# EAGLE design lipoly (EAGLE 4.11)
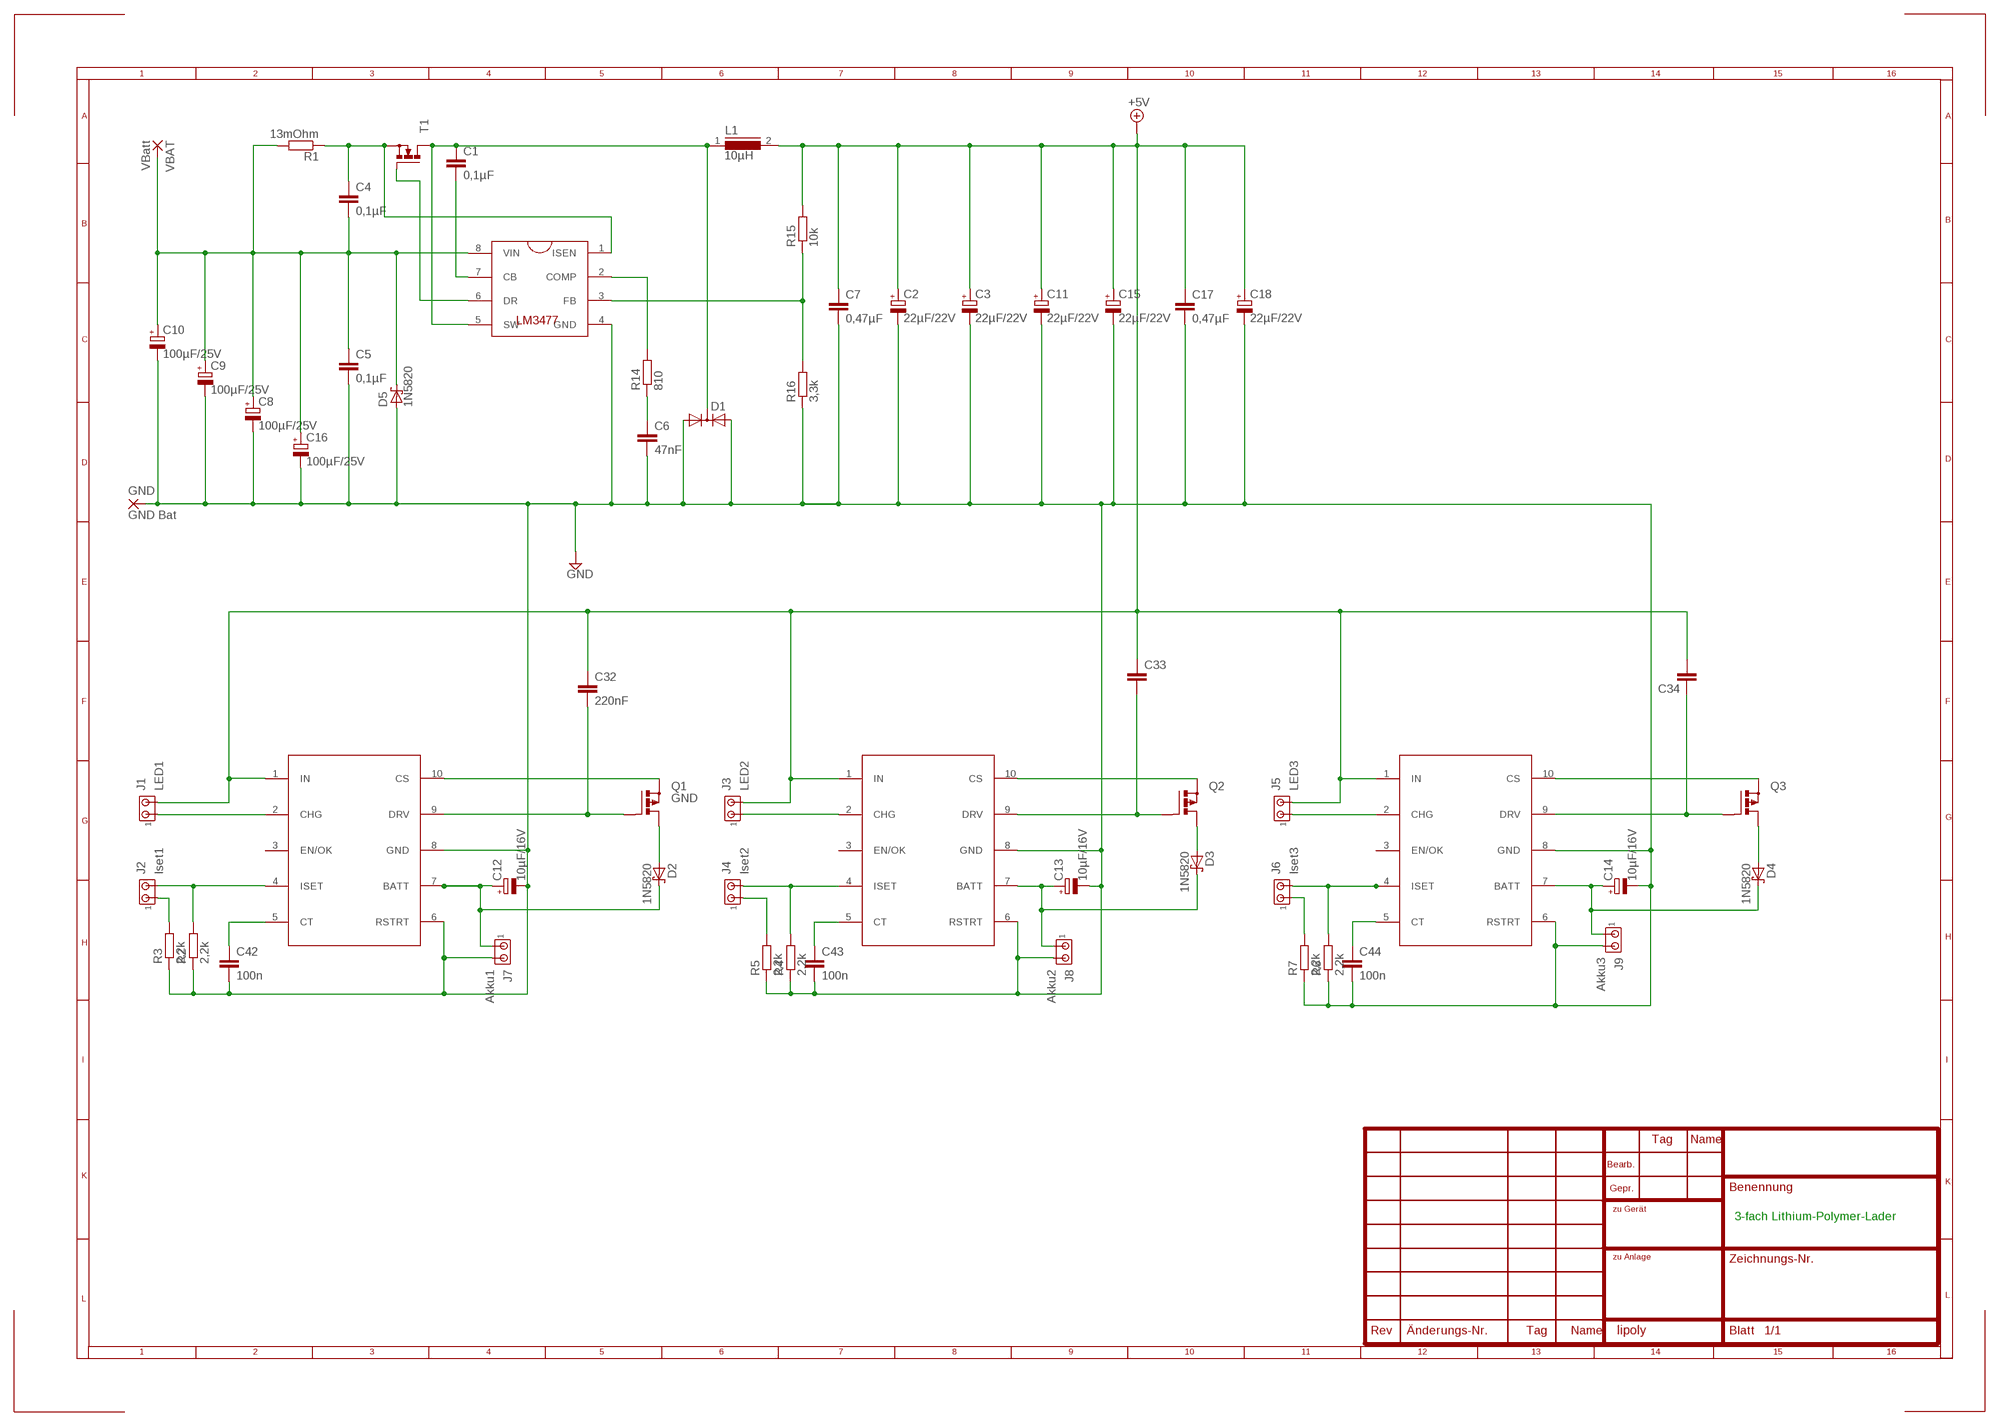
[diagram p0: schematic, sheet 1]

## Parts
C1  0,1µF  C-EU050-025X075  [C050-025X075]
C2  22µF/22V  CPOL-EUE5-6  [E5-6]
C3  22µF/22V  CPOL-EUE5-6  [E5-6]
C4  0,1µF  C-EU050-025X075  [C050-025X075]
C5  0,1µF  C-EU050-025X075  [C050-025X075]
C6  47nF  C-EU050-025X075  [C050-025X075]
C7  0,47µF  C-EU050-025X075  [C050-025X075]
C8  100µF/25V  CPOL-EUTT5D10  [TT5D10]
C9  100µF/25V  CPOL-EUTT5D10  [TT5D10]
C10  100µF/25V  CPOL-EUTT5D10  [TT5D10]
C11  22µF/22V  CPOL-EUE5-6  [E5-6]
C12  10µF/16V  CPOL-EUTAP5-60  [TAP5-60]
C13  10µF/16V  CPOL-EUTAP5-60  [TAP5-60]
C14  10µF/16V  CPOL-EUTAP5-60  [TAP5-60]
C15  22µF/22V  CPOL-EUE5-6  [E5-6]
C16  100µF/25V  CPOL-EUTT5D10  [TT5D10]
C17  0,47µF  C-EU050-025X075  [C050-025X075]
C18  22µF/22V  CPOL-EUE5-6  [E5-6]
C32  220nF  C-EU050-050X075  [C050-050X075]
C33  C-EU050-050X075  [C050-050X075]
C34  C-EU050-050X075  [C050-050X075]
C42  100n  C-EU050-025X075  [C050-025X075]
C43  100n  C-EU050-025X075  [C050-025X075]
C44  100n  C-EU050-025X075  [C050-025X075]
D1  DIODE-2AC|CATO220V  [TO220ABS]
D2  1N5820  SCHOTTKY-DIODEC4111-15  [C4111-15]
D3  1N5820  SCHOTTKY-DIODEC4111-15  [C4111-15]
D4  1N5820  SCHOTTKY-DIODEC4111-15  [C4111-15]
D5  1N5820  SCHOTTKY-DIODEC4111-15  [C4111-15]
GND  GND Bat  2,54/1,1  [2,54/1,1]
IC2  MAX1898  [UMAX10@1]
IC3  MAX1898  [UMAX10@1]
IC4  MAX1898  [UMAX10@1]
J1  LED1  MTA02-100  [10X02MTA]
J2  Iset1  MTA02-100  [10X02MTA]
J3  LED2  MTA02-100  [10X02MTA]
J4  Iset2  MTA02-100  [10X02MTA]
J5  LED3  MTA02-100  [10X02MTA]
J6  Iset3  MTA02-100  [10X02MTA]
J7  Akku1  MTA02-100  [10X02MTA]
J8  Akku2  MTA02-100  [10X02MTA]
J9  Akku3  MTA02-100  [10X02MTA]
L1  10µH  SFT830D  [SFT830D]
Q1  GND  PMOSFET_PTO220BV  [TO220BV]
Q2  PMOSFET_PTO220BV  [TO220BV]
Q3  PMOSFET_PTO220BV  [TO220BV]
R1  13mOhm  R-EU_0309/12  [0309/12]
R2  2,2k  R-EU_0207/10  [0207/10]
R3  2,2k  R-EU_0207/10  [0207/10]
R4  2,2k  R-EU_0207/10  [0207/10]
R5  2,2k  R-EU_0207/10  [0207/10]
R6  2,2k  R-EU_0207/10  [0207/10]
R7  2,2k  R-EU_0207/10  [0207/10]
R14  810  R-EU_0207/10  [0207/10]
R15  10k  R-EU_0207/10  [0207/10]
R16  3,3k  R-EU_0207/10  [0207/10]
T1  PMOSFET_NTO220BV  [TO220BV]
U$2  LM3477  [MINI-SO]
VBAT  VBatt  2,54/1,1  [2,54/1,1]

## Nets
+5V: C2.+ C3.+ C7.1 C11.+ C15.+ C17.1 C18.+ C32.1 C33.1 C34.2 IC2.1(IN) IC3.1(IN) IC4.1(IN) J1.2 J3.2 J5.2 L1.2 R15.2
+12V: C4.2 C5.1 C8.+ C9.+ C10.+ C16.+ D5.C R1.2 U$2.8(VIN) VBAT.1(P)
C42: C42.1 IC2.5(CT)
GND: C2.- C3.- C5.2 C6.2 C7.2 C8.- C9.- C10.- C11.- C12.- C13.- C14.- C15.- C16.- C17.2 C18.- C42.2 C43.2 C44.2 D1.A1 D1.A2 D5.A GND.1(P) IC2.6(RSTRT) IC2.8(GND) IC3.6(RSTRT) IC3.8(GND) IC4.6(RSTRT) IC4.8(GND) J7.2 J8.2 J9.2 R2.1 R3.1 R4.1 R5.1 R6.1 R7.1 R16.1 U$2.4(GND)
N$2: T1.G U$2.6(DR)
N$3: C4.1 R1.1 T1.S U$2.1(ISEN)
N$4: C1.1 D1.C L1.1 T1.D U$2.5(SW)
N$5: R14.2 U$2.2(COMP)
N$6: C1.2 U$2.7(CB)
N$7: IC2.10(CS) Q1.S
N$8: C6.1 R14.1
N$9: J4.1 R5.2
N$10: J6.1 R7.2
N$11: C32.2 IC2.9(DRV) Q1.G
N$12: J2.1 R3.2
N$13: R15.1 R16.2 U$2.3(FB)
N$14: C13.+ D3.C IC3.7(BATT) J8.1
N$25: C33.2 IC3.9(DRV) Q2.G
N$26: D3.A Q2.D
N$27: C12.+ D2.C IC2.7(BATT) J7.1
N$28: IC4.10(CS) Q3.S
N$29: C34.1 IC4.9(DRV) Q3.G
N$32: C14.+ D4.C IC4.7(BATT) J9.1
N$33: IC2.2(CHG) J1.1
N$34: IC2.4(ISET) J2.2 R2.2
N$35: IC3.4(ISET) J4.2 R4.2
N$36: IC4.4(ISET) J6.2 R6.2
N$37: C43.1 IC3.5(CT)
N$38: IC3.2(CHG) J3.1
N$39: C44.1 IC4.5(CT)
N$40: IC4.2(CHG) J5.1
T2: D2.A Q1.D
T3: IC3.10(CS) Q2.S
T4: D4.A Q3.D
Unconnected: IC2.3(EN/OK) IC3.3(EN/OK) IC4.3(EN/OK)

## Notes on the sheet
- 3-fach Lithium-Polymer-Lader

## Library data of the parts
C1 C4-C7 C17 C32-C34 C42-C44 = rcl:C-EU: CAPACITOR, European symbol
C2 C3 C8-C16 C18 = rcl:CPOL-EU: POLARIZED CAPACITOR, European symbol
D1 = diode:DIODE-2AC|CA: Dual DIODE Anode-Cathode|Cathode-Anode
D2-D5 = diode:SCHOTTKY-DIODE: Schottky Diode
GND VBAT = wirepad:2,54/1,1: THROUGH-HOLE PAD
IC2-IC4 = maxim:MAX1898
J1-J9 = con-amp:MTA02-100: AMP connector
L1 = inductors:SFT830D: INDUCTOR
Q1-Q3 = transistor-power:PMOSFET_P: Power MOSFET P-Channel
R1-R7 R14-R16 = rcl:R-EU_: RESISTOR, European symbol
T1 = transistor-power:PMOSFET_N: Power MOSFET N-Channel
U$2 = national:LM3477

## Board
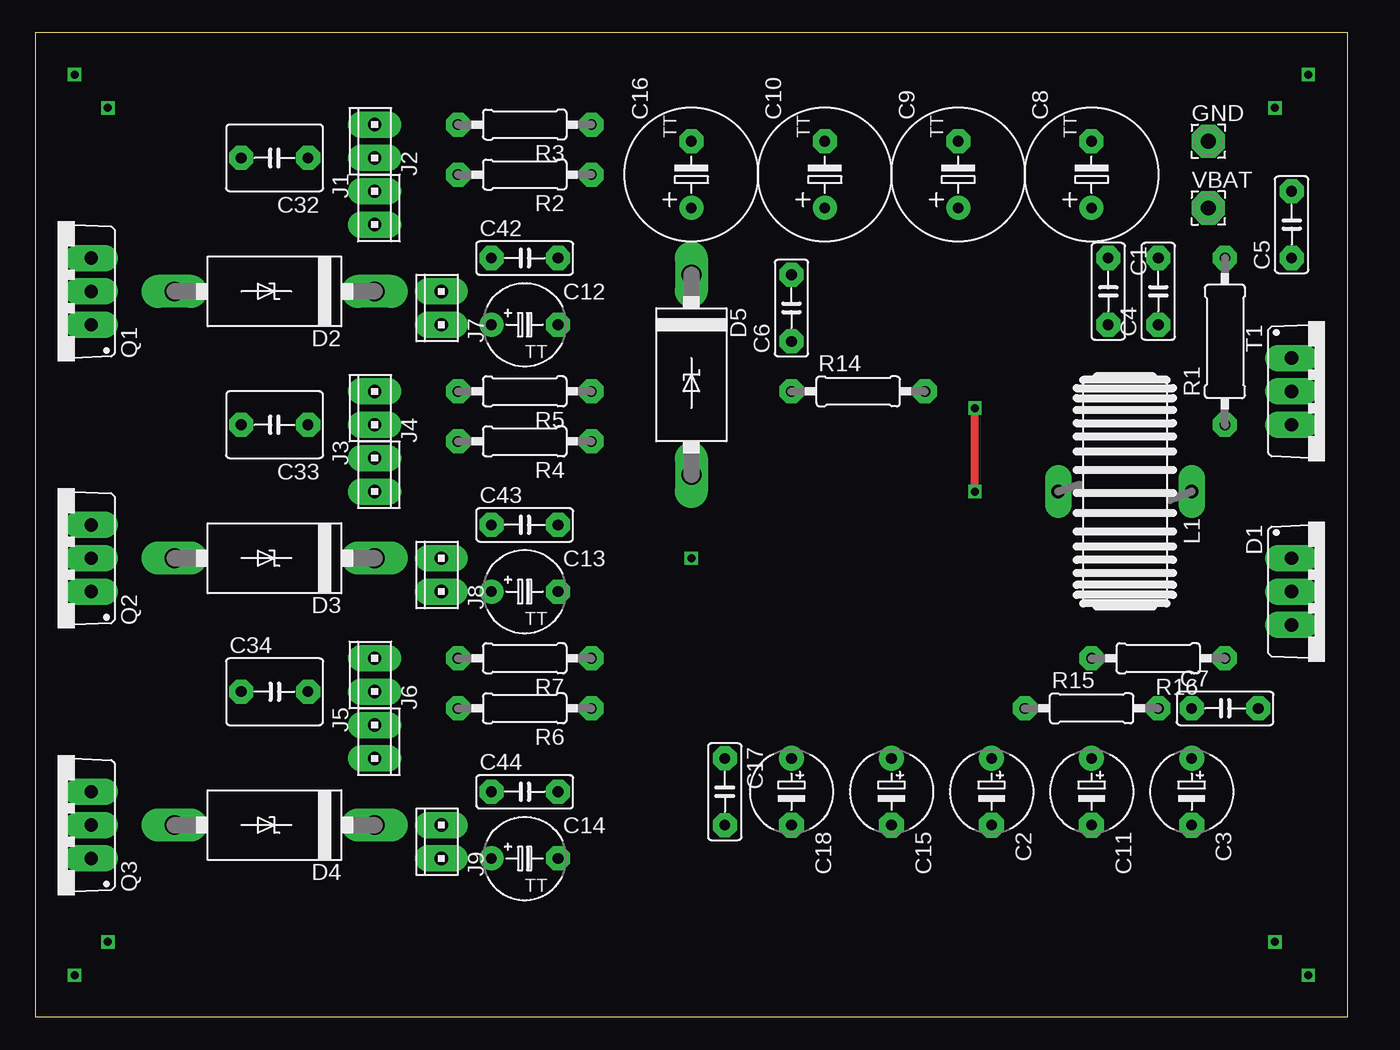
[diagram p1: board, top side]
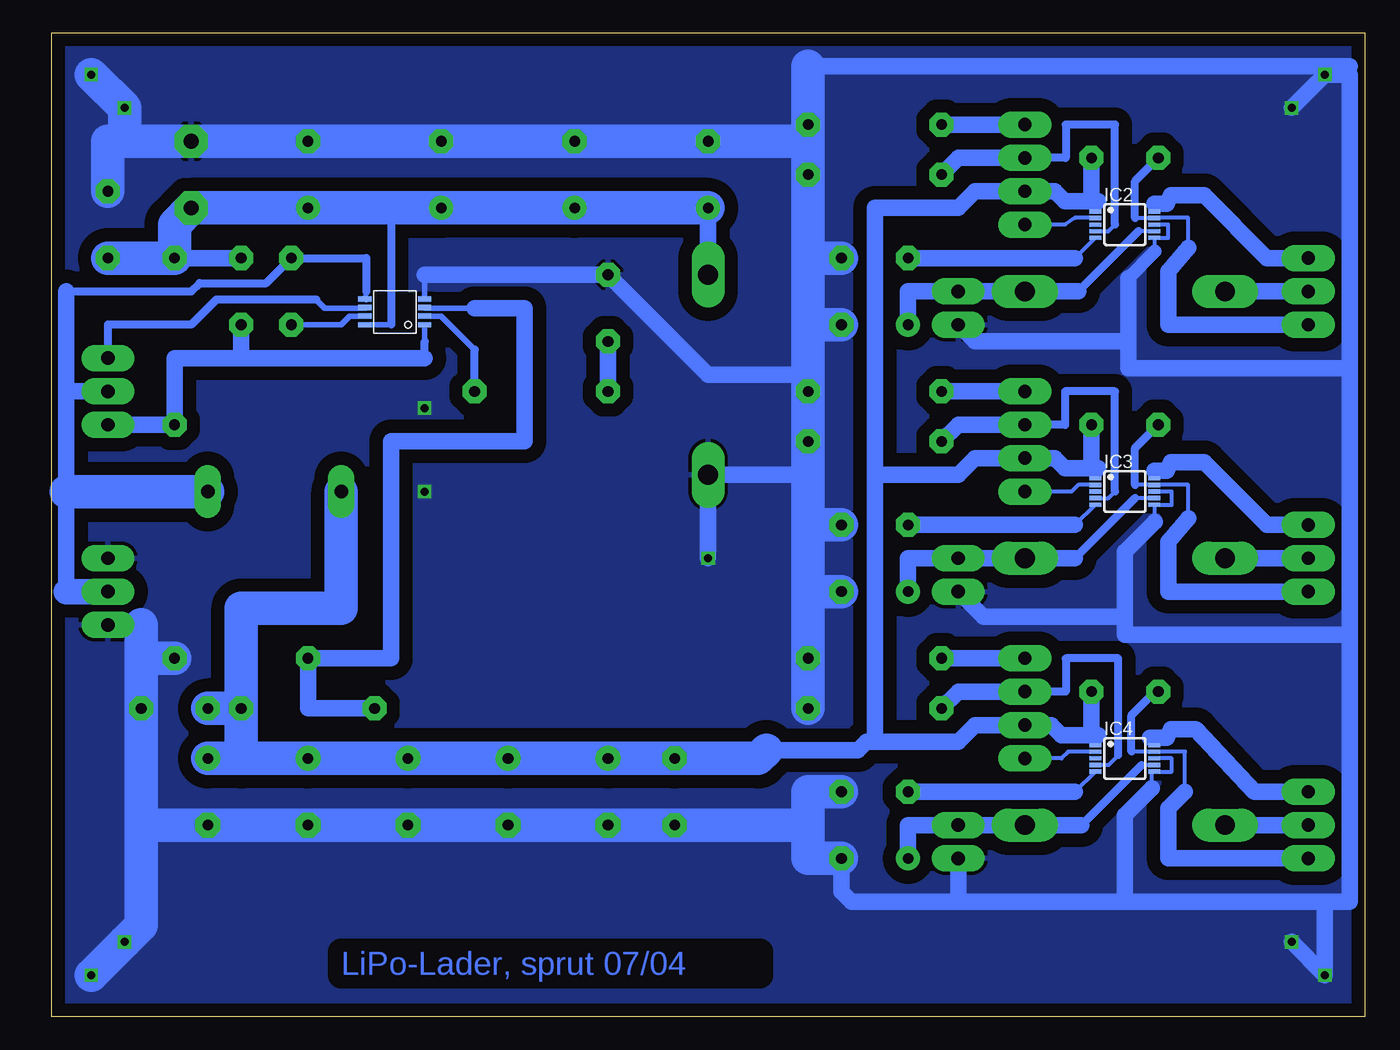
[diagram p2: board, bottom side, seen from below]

Size 100 x 74.92 mm. Coordinates in mm from the lower left corner, seen from the top.
Outline: 0,0 100,0 100,74.92 0,74.92 0,0
Copper layers (1*16): Top 0.035mm / dielectric 1.5mm / Bottom 0.035mm
Design rules "default": minimum track width 10mil, minimum drill 12mil, track to track 8mil, track to pad 8mil, pad to pad 8mil, via to via 8mil, smd to smd 8mil, copper to edge 40mil, drill to drill 8mil, minimum pad ring 20mil, minimum via ring 8mil, stop-mask expansion 4mil, vias tented up to drill 0mil, thermal gap 10mil

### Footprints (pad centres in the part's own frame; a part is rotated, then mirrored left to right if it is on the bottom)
C050-025X075 = drill 0.813 pad 1.778 octagon: 1 -2.54,0; 2 2.54,0
E5-6 = drill 0.813 pad 1.905 round: + -2.54,0 | drill 0.813 pad 1.905 octagon: - 2.54,0
TT5D10 = drill 0.813 round: + -2.54,0 | drill 0.813 octagon: - 2.54,0
TAP5-60 = drill 0.813 round: + -2.54,0 | drill 0.813 octagon: - 2.54,0
C050-050X075 = drill 0.813 octagon: 1 -2.54,0; 2 2.54,0
TO220ABS = drill 1.016 long: A1 -2.54,-2.54; A2 2.54,-2.54; C 0,-2.54
C4111-15 = drill 1.499 long: A 7.62,0; C -7.62,0
2,54/1,1 = drill 1.118 pad 2.54 octagon: 1 0,0
UMAX10@1 = smd 0.32 x 0.9: 1 -1,-2.25; 2 -0.5,-2.25; 3 0,-2.25; 4 0.5,-2.25; 5 1,-2.25; 6 1,2.25; 7 0.5,2.25; 8 0,2.25; 9 -0.5,2.25; 10 -1,2.25
10X02MTA = drill 1.016 long: 1 1.27,0; 2 -1.27,0
SFT830D = drill 1.016 long: 1 -5.08,0; 2 5.08,0
TO220BV = drill 1.016 long: D 0,-2.54; G -2.54,-2.54; S 2.54,-2.54
0309/12 = drill 0.813 octagon: 1 -6.35,0; 2 6.35,0
0207/10 = drill 0.813 pad 1.778 octagon: 1 -5.08,0; 2 5.08,0
MINI-SO = smd 1.02 x 0.41: 1 -2.54,0; 2 -2.54,-0.65; 3 -2.54,-1.3; 4 -2.54,-1.95; 5 2.01,-1.95; 6 2.01,-1.3; 7 2.01,-0.65; 8 2.01,0

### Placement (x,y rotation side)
C1  81.75,55.24 270 top
C2  72.86,17.14 270 top
C3  88.1,17.14 270 top
C4  85.56,55.24 90 top
C5  95.72,60.32 90 top
C6  57.62,53.97 90 top
C7  90.64,23.49 0 top
C8  80.48,64.13 90 top
C9  70.32,64.13 90 top
C10  60.16,64.13 90 top
C11  80.48,17.14 270 top
C12  37.3,52.7 0 top
C13  37.3,32.38 0 top
C14  37.3,12.06 0 top
C15  65.24,17.14 270 top
C16  50,64.13 90 top
C17  52.54,17.14 270 top
C18  57.62,17.14 270 top
C32  18.25,65.4 180 top
C33  18.25,45.08 180 top
C34  18.25,24.76 0 top
C42  37.3,57.78 0 top
C43  37.3,37.46 0 top
C44  37.3,17.14 0 top
D1  98.26,32.38 270 top
D2  18.25,55.24 180 top
D3  18.25,34.92 180 top
D4  18.25,14.6 180 top
D5  50,48.89 270 top
GND  89.37,66.67 0 top
IC2  18.25,60.32 270 bottom
IC3  18.25,40 270 bottom
IC4  18.25,19.68 270 bottom
J1  25.87,61.59 270 top
J2  25.87,66.67 90 top
J3  25.87,41.27 270 top
J4  25.87,46.35 90 top
J5  25.87,20.95 270 top
J6  25.87,26.03 90 top
J7  30.95,53.97 90 top
J8  30.95,33.65 90 top
J9  30.95,13.33 90 top
L1  83.02,40 180 top
Q1  1.74,55.24 90 top
Q2  1.74,34.92 90 top
Q3  1.74,14.6 90 top
R1  90.64,51.43 90 top
R2  37.3,64.13 180 top
R3  37.3,67.94 180 top
R4  37.3,43.81 180 top
R5  37.3,47.62 180 top
R6  37.3,23.49 180 top
R7  37.3,27.3 180 top
R14  62.7,47.62 0 top
R15  80.48,23.49 0 top
R16  85.56,27.3 180 top
T1  98.26,47.62 270 top
U$2  74.13,52.7 180 bottom
VBAT  89.37,61.59 0 top

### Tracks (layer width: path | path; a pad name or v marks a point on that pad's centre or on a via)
+5V
  Bottom 0.254: J3.2 25.62,42.54 | 20.52,41 20.54,41.02 | 20.52,41 IC3.1 | 20.52,61.32 20.54,61.34 | 20.52,61.32 IC2.1 | 20.15,62.22 20.28,62.1 20.52,61.86 20.52,61.32 | 20.15,41.9 20.28,41.78 20.52,41.54 20.52,41 | 20.15,21.59 20.28,21.46 20.5,21.24 IC4.1
  Bottom 0.406: R15.2 C7.1 | C18.+ C17.1 C18.+ | C18.+ C15.+
  Bottom 1.27: 37.3,20.95 37.3,41.27 | 37.3,41.27 37.3,61.59 30.95,61.59 29.68,62.86 J1.2 23.58,62.86 22.82,62.1 20.79,62.1 | J3.2 29.68,42.54 30.95,41.27 37.3,41.27 | 37.3,20.95 30.95,20.95 29.68,22.22 J5.2 23.84,22.22 23.08,21.46 20.79,21.46 | 20.79,62.1 20.28,62.1 | 20.79,62.1 C32.1 | 25.62,42.54 23.58,42.54 22.82,41.78 20.79,41.78 | 20.79,41.78 20.28,41.78 | 20.79,41.78 C33.1 | 20.28,21.46 20.79,21.46 | 20.79,21.46 C34.2 | 37.3,20.95 37.94,20.95 38.57,20.32 45.55,20.32
  Bottom 2.54: R15.2 C7.1 | L1.2 77.94,31.11 85.56,31.11 R15.2 | 85.56,19.68 C11.+ C2.+ C15.+ C18.+ C17.1 46.19,19.68 45.55,20.32 | 85.56,19.68 C3.+ | 85.56,19.68 R15.2
+12V
  Bottom 0.406: 74.13,52.7 U$2.8
  Bottom 0.61: 74.13,61.59 74.13,52.7
  Bottom 1.27: R1.2 C4.2 | D5.C C16.+
  Bottom 2.54: 74.13,61.59 C10.+ C16.+ | 74.13,61.59 C9.+ | 74.13,61.59 C8.+ VBAT.1 90.64,60.32 R1.2 C5.1
C42
  Bottom 0.254: IC2.5 20.52,59.32
  Bottom 0.305: 20.52,59.32 22.06,57.78
  Bottom 1.27: 22.06,57.78 C42.1
GND  (via drill 0.61)
  Top 0.61: v71.59,40 v71.59,46.35
  Bottom 0.254: 15.96,18.66 15.98,18.68 IC4.6 16.2,18.68 | 16.22,38.98 15.98,39 IC3.6 16.2,39 16.22,38.98 | 15.96,38.98 16.22,38.98 | 42.13,57.78 42.13,67.69 R3.1
  Bottom 0.305: IC4.8 14.69,19.68 14.69,18.66 15.96,18.66 | 16.22,17.39 16.2,18.68 | IC3.8 14.69,40 14.69,38.98 15.96,38.98 15.96,37.71 | C42.2 42.38,57.78 42.38,66.67 | 1.1,49.4 1.1,49.52 1.23,49.4 | 1.1,29.08 1.1,29.21 1.23,29.08 | 15.96,58.29 15.96,59.3 | IC2.8 14.95,60.32 14.95,59.3 15.96,59.3 | 15.96,59.3 15.98,59.32 IC2.6
  Bottom 0.406: 71.59,56.51 U$2.4
  Bottom 1.016: 1.1,29.08 18.25,29.08 | 1.1,49.4 18,49.4 | 18,56.26 15.96,58.29
  Bottom 1.27: 3.01,8.76 1.1,8.76 1.1,29.21 1.1,49.52 1.1,71.75 v3.01,71.75 | 3.01,8.76 18.25,8.76 | 18.25,8.76 18.25,15.36 16.22,17.39 | 18,51.43 18,49.4 1.23,49.4 | 18,51.43 18,56.26 | 15.96,37.71 18.25,35.43 18.25,30.47 | 18.25,30.47 18.25,29.08 1.23,29.08 | 3.01,72.38 42.38,72.38 | v3.01,71.75 3.01,72.38 | 3.01,72.38 1.1,72.38 | 3.01,8.76 v3.01,3.17 v5.55,5.71 | v3.01,71.75 v5.55,69.21 | 18.25,8.76 30.95,8.76 | 30.95,8.76 39.08,8.76 39.84,9.52 C14.- | 94.45,66.67 95.72,66.67 | J7.2 29.68,51.43 18,51.43 | J8.2 29.04,30.47 18.25,30.47 | 30.95,8.76 J9.2 | 71.59,56.51 C6.2 50,48.89 42.38,48.89 | 42.38,41.27 D5.A v50,34.92
  Bottom 2.54: 93.18,27.3 C7.2 93.18,14.6 | 93.18,27.3 93.18,29.84 | 93.18,27.3 R16.1 | R6.1 R7.1 42.38,32.38 | 42.38,37.46 42.38,32.38 | 42.38,37.46 42.38,41.27 R4.1 R5.1 42.38,48.89 42.38,52.7 | 42.38,57.78 42.38,52.7 | 42.38,57.78 R2.1 42.38,66.67 | 42.38,66.67 R3.1 42.38,72.38 | 42.38,57.78 42.13,57.78 C42.2 | 42.38,37.46 C43.2 | C44.2 42.38,17.14 42.38,14.6 | C14.- 42.38,12.06 42.38,14.6 | 42.38,32.38 C13.- | 42.38,52.7 C12.- | 93.18,14.6 C3.- C11.- C2.- C15.- 42.38,14.6 | v96.99,71.75 v94.45,69.21 94.45,66.67 GND.1 C8.- C9.- C10.- C16.- 42.38,66.67 | v96.99,3.17 v94.45,5.71 93.18,6.98 93.18,14.6 | 95.72,66.67 C5.2
  pour Bottom (isolate 1.016): 0.47,0.63 0.47,74.29 99.53,74.29 99.53,0.63
N$2
  Bottom 0.406: 79.84,54.6 79.21,53.97 76.03,53.97 76.03,54 U$2.6
  Bottom 0.61: 79.84,54.6 87.47,54.6 89.37,52.7 95.72,52.7 T1.G
N$3
  Bottom 0.406: 71.59,51.43 U$2.1
  Bottom 0.61: 71.59,50.16 71.59,51.43
  Bottom 1.27: 71.59,50.16 85.56,50.16 | 85.56,50.16 90.64,50.16 R1.1 T1.S | 85.56,50.16 C4.1
N$4
  Bottom 0.406: 76.08,54.65 76.03,54.6 | 76.08,54.65 U$2.5 | 76.03,55.24 76.08,54.65
  Bottom 0.61: 76.03,55.24 76.03,57.78 C1.1 83.66,55.88 88.73,55.88 89.37,55.24 98.89,55.24
  Bottom 1.27: 98.89,47.62 98.89,40 98.89,32.38 | 98.89,47.62 98.89,55.24 | 98.89,47.62 T1.D
  Bottom 1.93: D1.C 98.89,32.38
  Bottom 2.54: 98.89,40 L1.1
N$5
  Bottom 0.406: 67.78,50.79 70.32,53.33 71.59,53.33 U$2.2
  Bottom 0.61: R14.2 67.78,50.79
N$6
  Bottom 0.406: C1.2 77.94,52.7 77.3,53.33 76.03,53.33 76.05,53.35 U$2.7
N$7
  Bottom 0.254: IC2.10 15.98,61.32 15.96,61.34 15.96,61.84
  Bottom 1.27: Q1.S 7.46,57.78 12.22,62.54 14.76,62.54 15.08,61.91 16.03,61.91 15.96,61.84
N$8
  Bottom 1.27: R14.1 C6.1
N$9
  Bottom 1.27: J4.1 R5.2
N$10
  Bottom 1.27: J6.1 R7.2
N$11
  Bottom 0.254: 17.48,60.82 17.49,60.83 | 15.96,60.83 15.97,60.82 IC2.9
  Bottom 0.305: IC2.9 17.48,60.82 | 13.42,58.54 13.42,60.83 15.96,60.83
  Bottom 0.61: 17.49,60.83 17.49,63.62 C32.2
  Bottom 1.27: Q1.G 14.95,52.7 14.95,56.76 13.42,58.54
N$12
  Bottom 1.27: J2.1 R3.2
N$13
  Bottom 0.406: U$2.3 71.59,53.97 67.78,53.97
  Bottom 1.27: R15.1 80.48,23.49 R16.2 74.13,27.3 74.13,43.81 63.97,43.81 63.97,53.97 67.78,53.97
N$14
  Bottom 0.254: 17.23,39.5 17.23,39.49 17.49,39.49
  Bottom 0.305: IC3.7 17.23,39.5
  Bottom 0.61: 17.49,39.49 22.06,34.92
  Bottom 1.27: 22.06,34.92 D3.C J8.1 34.76,34.92 C13.+
N$25
  Bottom 0.254: 17.48,40.5 17.49,40.51 | 15.96,40.51 15.97,40.5 IC3.9
  Bottom 0.305: IC3.9 17.48,40.5 | 13.42,37.97 13.42,40.51 15.96,40.51
  Bottom 0.61: 17.49,40.51 17.49,43.3 C33.2
  Bottom 1.27: Q2.G 14.95,32.38 14.95,36.19 13.42,37.97
N$26
  Bottom 1.27: Q2.D D3.A
N$27
  Bottom 0.305: IC2.7 17.23,59.82
  Bottom 0.61: 17.23,59.82 21.81,55.24
  Bottom 1.27: 21.81,55.24 D2.C J7.1 34.76,55.24 C12.+
N$28
  Bottom 0.254: IC4.10 15.98,20.68 15.96,20.7 15.92,21.23 15.9,21.52
  Bottom 0.61: 16.34,21.27 15.92,21.23
  Bottom 1.27: Q3.S 8.41,17.14 12.85,21.9 14.76,21.9 15.08,21.27 16.34,21.27
N$29
  Bottom 0.254: 13.68,20.19 13.69,20.18 | 15.96,20.19 15.97,20.18 IC4.9
  Bottom 0.305: 13.69,20.18 IC4.9 | 13.68,17.14 13.68,20.19 | 15.96,20.19 17.74,20.19
  Bottom 0.61: C34.1 15.96,24.76 17.74,22.98 17.74,20.19
  Bottom 1.27: 13.68,17.14 14.95,15.87 14.95,12.06 Q3.G
N$32
  Bottom 0.254: 15.96,19.17 15.97,19.18 IC4.7
  Bottom 0.305: 15.96,19.17 16.98,19.17
  Bottom 0.61: 16.98,19.17 21.55,14.6
  Bottom 1.27: 21.55,14.6 D4.C J9.1 34.76,14.6 C14.+
N$33
  Bottom 0.254: 20.54,60.83 20.53,60.82 IC2.2
  Bottom 0.305: J1.1 22.82,60.32 22.06,60.83 20.54,60.83
N$34
  Bottom 0.254: 19.53,59.82 19.52,59.81
  Bottom 0.305: IC2.4 19.53,59.82 | 19.52,59.81 19.01,60.32
  Bottom 0.61: 19.01,60.32 19.01,67.94 22.76,67.94 22.76,65.4 J2.2
  Bottom 1.27: R2.2 30.95,65.4 J2.2
N$35
  Bottom 0.254: 19.53,39.5 19.52,39.49
  Bottom 0.305: IC3.4 19.53,39.5 | 19.52,39.49 19.01,40
  Bottom 0.61: 19.01,40 19.01,47.62 22.82,47.62 22.82,45.08 J4.2
  Bottom 1.27: J4.2 30.95,45.08 R4.2
N$36
  Bottom 0.254: 19.53,19.18 19.52,19.17
  Bottom 0.305: IC4.4 19.53,19.18 | 19.52,19.17 18.76,19.93
  Bottom 0.61: 18.76,19.93 18.76,27.3 22.76,27.3 22.76,24.76 J6.2
  Bottom 1.27: J6.2 30.95,24.76 R6.2
N$37
  Bottom 0.254: IC3.5 20.52,39
  Bottom 0.305: 20.52,39 22.06,37.46
  Bottom 1.27: 22.06,37.46 C43.1
N$38
  Bottom 0.254: 20.54,40.51 20.53,40.5 IC3.2
  Bottom 0.305: J3.1 22.31,40 21.81,40.51 20.54,40.51
N$39
  Bottom 0.254: IC4.5 20.52,18.68
  Bottom 0.305: 20.52,18.68 22.06,17.14
  Bottom 1.27: 22.06,17.14 C44.1
N$40
  Bottom 0.305: J5.1 23.08,19.68 22.57,20.19 20.54,20.19 20.53,20.18 IC4.2
T2
  Bottom 1.27: Q1.D D2.A
T3
  Bottom 0.254: IC3.10 15.98,41 15.96,41.02 15.96,41.52
  Bottom 1.27: Q2.S 7.46,37.46 12.22,42.22 14.76,42.22 15.08,41.59 16.03,41.59 15.96,41.52
T4
  Bottom 1.27: Q3.D D4.A

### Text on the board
Bottom: LiPo-Lader, sprut 07/04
